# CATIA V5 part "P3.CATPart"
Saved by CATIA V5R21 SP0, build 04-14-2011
Part number: Part1
Bounding box of the stored display mesh (mm): x 0 to 77, y -41 to 41, z -19 to 21
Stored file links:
  C:\Users\HP\Desktop\Mes Fichiers\catia lesson\Mini Projet\Projet 1\P3.CATPart
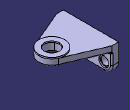
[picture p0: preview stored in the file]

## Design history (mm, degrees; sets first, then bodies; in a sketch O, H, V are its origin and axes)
AxisSystem1: origin (0, 0, 0), X (1, 0, 0), Y (0, 1, 0), Z (0, 0, 1)
Body1 (main body)
  Sketch1 on YZ plane of AxisSystem1, origin (0, 0, 0), H (0, 1, 0), V (0, 0, 1)
    line L1 (-41, 19) -> (41, 19)
    line L2 (41, 19) -> (41, -19)
    line L3 (41, -19) -> (-41, -19)
    line L4 (-41, -19) -> (-41, 19)
    length L3 = 82
    length L2 = 38
    horizontal: L1 H, L3 H
    vertical: L2 V, L4 V
    symmetry: L2 L4 V, L1 L3 H
  Pad1: profile Sketch1, direction (1, 0, 0), length 10
  Sketch2 on face of Pad1 from Sketch1.L1, origin (0, 0, 19), H (1, 0, 0), V (0, 1, 0)
    point P1 (10, 41)
    line L1 (10, 41) -> (65.4423, 17.397)
    arc A1 centre (58, -0.0847) radius 19 from (65.4423, 17.397) to (63.1465, -18.3744) cw
    point P3 (58, -0.0847)
    line L2 (63.1465, -18.3744) -> (10, -41)
    line L3 (10, -41) -> (10, 41)
    reference intersected line E1 through (0, 0) direction (-1, 0) from ZX plane of AxisSystem1
    reference projected point E2 (10, 41) from vertex [face of Pad1 from Sketch1.L1 | end face of Pad1 | face of Pad1 from Sketch1.L2]
    distance P3 L3 = 48
    radius A1 = 19
    tangency: A1 L1
    vertical: L3 V
    symmetry: L1 L2 E1
    coincidence: P1 E2
  Pad2: profile Sketch2, direction (0, 0, -1), length 10
  Fillet1: radius 12, on edge [face of Pad1 from Sketch1.L3 | face of Pad1 from Sketch1.L4]; edge [face of Pad1 from Sketch1.L2 | face of Pad1 from Sketch1.L3]
  Sketch3 on end face of Pad2, origin (0, 0, 9), H (1, 0, 0), V (0, -1, 0)
    point P1 (58, 0.0847)
    reference projected arc E1 centre (58, 0.0847) radius 19 from (65.4423, -17.397) to (63.1465, 18.3744) ccw from edge [end face of Pad2 | face of Pad2 from Sketch2.A1]
    concentricity: P1 E1
  Sketch4 on end face of Pad2, origin (58, -0.0847, 9), H (1, 0, 0), V (0, -1, 0)
    point P1 (0, 0)
    reference projected point E1 (0, 0) from Sketch3.P1
    coincidence: E1 P1
  Hole1: placed by Sketch4, at (58, -0.0847, 9) direction (0, 0, 1), diameter 22, depth 10
  Sketch5 on face of Pad2, origin (0, 0, 19), H (1, 0, 0), V (0, 1, 0)
    circle A1 centre (58, -0.0847) radius 19
    reference projected arc E1 centre (58, -0.0847) radius 19 from (63.1465, -18.3744) to (65.4423, 17.397) ccw from edge [face of Pad2 from Sketch2.A1 | start face of Pad2]
    circle A2 centre (58, -0.0847) radius 11
    reference projected circle E2 centre (58, -0.0847) radius 11 from edge [face of Pad2 | face of Hole1]
    coincidence: A1 E1, A2 E2
  Pad3: profile Sketch5, direction (0, 0, 1), length 2
  Fillet2: radius 2, on edge [end face of Pad2 | face of Pad2 from Sketch2.L2]
  Fillet3: radius 2, on edge [end face of Pad2 | face of Pad2 from Sketch2.L1]
  Fillet4: radius 2, on edge [end face of Pad2 | end face of Pad1]; edge [face of Pad1 from Sketch1.L2 | end face of Pad1]; edge [end face of Pad1 | face of Fillet1] (x2); edge [face of Pad1 from Sketch1.L3 | end face of Pad1]; end face of Pad1
  Sketch6 on end face of Pad1, origin (10, 0, 0), H (0, 1, 0), V (0, 0, 1)
    point P1 (29, -7)
    reference projected arc E1 centre (29, -7) radius 12 from (29, -19) to (41, -7) ccw from edge [face of Fillet1 | face of Fillet4]
    reference projected line E2 through (0, 0) direction (0, 1) from edge [ZX plane of AxisSystem1 | YZ plane of AxisSystem1]
    point P4 (-29, -7)
    construction line L1 through (0, 0) direction (0, 1)
    concentricity: P1 E1
    symmetry: P1 P4 E2, V L1 E2
  Sketch7 on end face of Pad1, origin (10, 29, -7), H (0, 1, 0), V (0, 0, 1)
    point P1 (0, 0)
    reference projected point E1 (0, 0) from Sketch6.P1
    coincidence: E1 P1
  Hole2: placed by Sketch7, at (10, 29, -7) direction (-1, 0, 0), diameter 12, through (limit type 3), counterbore diameter 15, counterbore depth 2
  Sketch8 on end face of Pad1, origin (10, -29, -7), H (0, 1, 0), V (0, 0, 1)
    point P1 (0, 0)
    reference projected point E1 (0, 0) from Sketch6.P4
    coincidence: E1 P1
  Hole3: placed by Sketch8, at (10, -29, -7) direction (-1, 0, 0), diameter 12, through (limit type 3), counterbore diameter 15, counterbore depth 2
